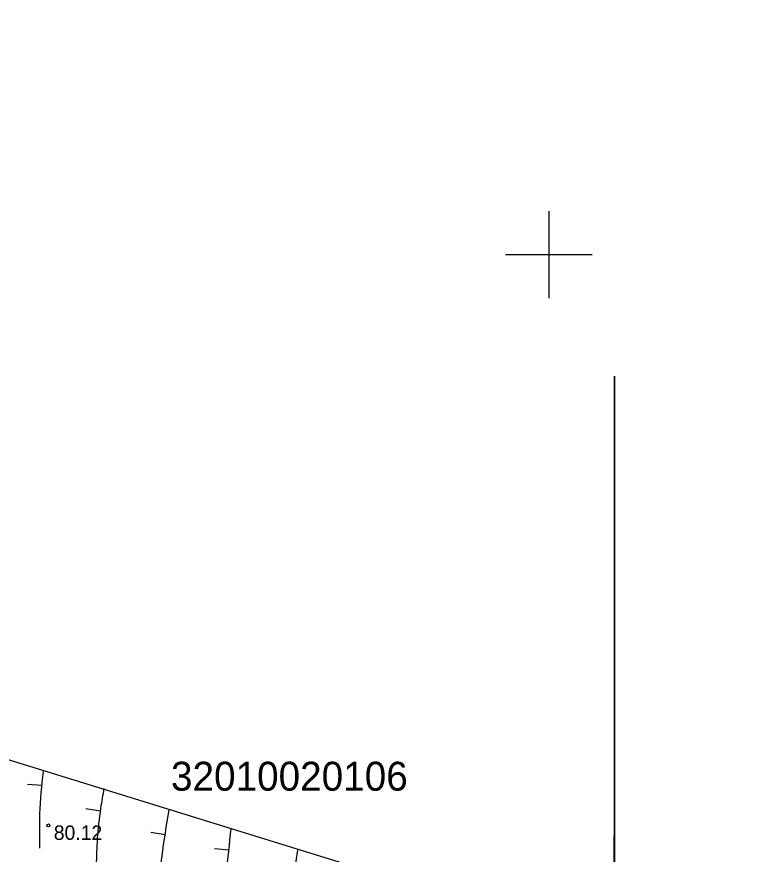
# Model space of a CAD drawing. Extents: x 576692 to 577659, y 273254 to 273799.
# Drawn here: x 577281.61 to 577306.99, y 273429.28 to 273458.22 of the extents above; entities that cross this region are included whole.
import ezdxf

# ---------------------------------------------------------------- set-up
doc = ezdxf.new("R2010")
doc.units = 0
for name, color, linetype in [('BUVE_EKAS_BPAL_####_#', 7, 'Continuous'), ('CELI_TAKA_####_####_#', 7, 'Continuous'), ('CKOM_ELEM_####_####_#', 7, 'Continuous'), ('GEOD_ELEM_####_TKST_#', 7, 'Continuous'), ('GEOD_SITP_####_TKST_#', 7, 'Continuous'), ('HIDT_REZV_####_TKST_#', 7, 'Continuous'), ('RELJ_ELEM_####_####_#', 7, 'Continuous'), ('SILT_VADP_UDEN_####_#', 7, 'Continuous')]:
    doc.layers.add(name, color=color, linetype=linetype)

msp = doc.modelspace()

# ---------------------------------------------------------------- linework, layer by layer
at = {"layer": 'CELI_TAKA_####_####_#'}
msp.add_lwpolyline([(577175.353, 273468.597), (577186.541, 273460.401), (577209.755, 273452.336), (577213.035, 273463.823), (577248.138, 273456.832), (577262.689, 273443.249), (577269.097, 273442.704), (577268.898, 273436.394), (577301.349, 273426.359), (577308.434, 273412.519), (577319.001, 273409.126), (577359.322, 273426.883), (577382.525, 273495.967), (577376.088, 273498.638), (577384.502, 273518.904), (577411.715, 273507.613), (577405.2, 273487.348), (577452.189, 273444.346)], dxfattribs=at)
at = {"layer": 'CKOM_ELEM_####_####_#'}
for p, q in [((577300, 273451.5), (577300, 273450)), ((577298.5, 273450), (577300, 273450)), ((577300, 273450), (577300, 273448.5)), ((577300, 273450), (577301.5, 273450))]:
    msp.add_line(p, q, dxfattribs=at)
at = {"layer": 'GEOD_ELEM_####_TKST_#'}
msp.add_line((577281.984, 273431.707), (577282.483, 273431.665), dxfattribs=at)
for points in [[(577282.522, 273432.138), (577282.4, 273430.685), (577282.4, 273429.743), (577282.401, 273429.495)], [(577291.312, 273429.428), (577291.139, 273428.229), (577291.053, 273427.662)]]:
    msp.add_spline(points, degree=3, dxfattribs=at)
at = {"layer": 'GEOD_SITP_####_TKST_#'}
for p, q in [((577284.003, 273430.861), (577284.497, 273430.784)), ((577286.241, 273430.046), (577286.736, 273429.97)), ((577288.444, 273429.488), (577288.941, 273429.432))]:
    msp.add_line(p, q, dxfattribs=at)
for points in [[(577284.625, 273431.559), (577284.51, 273430.869), (577284.394, 273429.823), (577284.358, 273428.91), (577284.366, 273426.615), (577284.226, 273424.924), (577283.917, 273422.949)], [(577286.864, 273430.815), (577286.621, 273429.219), (577286.461, 273427.167), (577286.43, 273426.188), (577286.366, 273425.445), (577285.828, 273421.762)], [(577287.781, 273420.917), (577288.005, 273422.143), (577288.511, 273425.715), (577288.685, 273427.151), (577288.848, 273428.616), (577289.025, 273430.173)]]:
    msp.add_spline(points, degree=3, dxfattribs=at)
at = {"layer": 'RELJ_ELEM_####_####_#'}
msp.add_circle((577282.706, 273430.28), 0.05, dxfattribs=at)
at = {"layer": 'SILT_VADP_UDEN_####_#'}
for points in [[(577302.27, 273445.801), (577302.254, 273414.066), (577272.786, 273380.42), (577268.009, 273412.497), (577233.841, 273424.529), (577096.144, 273448.16), (576853.83, 273507.082), (576865.33, 273530.143), (576887.167, 273533.699), (576886.027, 273541.27), (576883.637, 273560.163)], [(577302.27, 273445.801), (577302.254, 273414.066), (577272.786, 273380.42), (577268.009, 273412.497), (577233.841, 273424.529), (577096.144, 273448.16), (576853.83, 273507.082), (576865.33, 273530.143), (576887.167, 273533.699), (576886.027, 273541.27), (576883.81, 273558.799)], [(577368.863, 273511.974), (577393.627, 273501.735), (577368.017, 273418.909), (577315.625, 273397.603), (577302.254, 273414.066), (577302.27, 273445.801)]]:
    msp.add_lwpolyline(points, dxfattribs=at)

# ---------------------------------------------------------------- texts
at = {"layer": 'BUVE_EKAS_BPAL_####_#'}
msp.add_text('32010020106', height=1, dxfattribs=at).set_placement((577286.942, 273431.48))
at = {"layer": 'HIDT_REZV_####_TKST_#'}
msp.add_text(' 80.12', height=0.5, dxfattribs=at).set_placement((577282.706, 273429.78))

doc.saveas('drawing.dxf')
